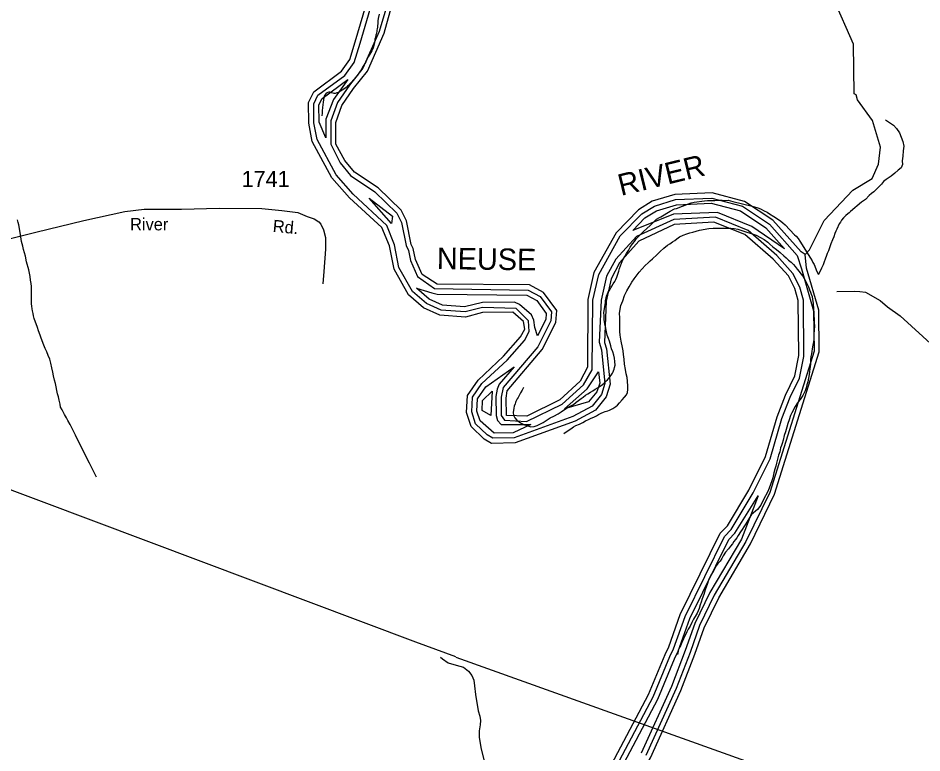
# Model space of a CAD drawing. Extents: x 2206922 to 2357709, y 510027 to 673830.
# Drawn here: x 2329174 to 2336184, y 547095 to 552793 of the extents above; entities that cross this region are included whole.
import ezdxf

# ---------------------------------------------------------------- set-up
doc = ezdxf.new("R2010")
doc.units = 0
for name, color, linetype in [('Exist Hydrographic Buffer Line', 7, 'Continuous'), ('Exist Hydrographic Creek Single Shore', 7, 'Continuous'), ('Exist Hydrographic Misc Water Feature', 7, 'Continuous'), ('Exist Hydrographic River Shore', 7, 'Continuous'), ('Exist Hydrographic River Shore Label', 7, 'Continuous'), ('Exist Road Non-System Type 51', 7, 'Continuous'), ('Exist Road Secondary Type 51 Attributed', 7, 'Continuous'), ('Exist Road Secondary Type 51 Label', 7, 'Continuous'), ('Exist Road Secondary Type 51 Number Label', 7, 'Continuous'), ('Exist Utilities Electrical Transmission Line', 7, 'Continuous')]:
    doc.layers.add(name, color=color, linetype=linetype)

msp = doc.modelspace()

# ---------------------------------------------------------------- linework, layer by layer
at = {"layer": 'Exist Hydrographic Buffer Line'}
for points in [[(2332099, 553109.3), (2331974.9, 552690.5), (2331848.2, 552403.8), (2331744.2, 552272.2), (2331651.8, 552138.5), (2331599.1, 551996.2), (2331598.6, 551814.8), (2331671.4, 551670.9), (2331752, 551572.5), (2331941.5, 551446.1), (2332111.1, 551280.1), (2332147.6, 551207.4), (2332182.4, 551030.3), (2332200.7, 550992.4), (2332216.5, 550913.4), (2332271.2, 550788.9), (2332403.3, 550697.5), (2333130.6, 550684.1), (2333222.7, 550635.1), (2333310.4, 550514.3), (2333304.5, 550444.7), (2333204.2, 550244.8), (2332936.2, 549929), (2332919.2, 549852.7), (2332920.8, 549711.9), (2332947.1, 549675), (2333117.1, 549665.8), (2333393.7, 549798.6), (2333558.9, 549949.1), (2333625, 550066.8), (2333631.7, 550606.3), (2333677.5, 550805.1), (2333844, 551104.3), (2334010.1, 551274.7), (2334108.5, 551336), (2334273.5, 551386), (2334553.4, 551397.3), (2334792.3, 551335.1), (2335000.3, 551196.3), (2335215.8, 550953.1)], [(2332340.5, 550580.5), (2332232.3, 550672.5), (2332127.7, 550859.6), (2332094, 551035.6), (2332032.7, 551185.4), (2331771.5, 551427.5), (2331640.7, 551577.7), (2331493, 551850.9), (2331468.6, 551981.4), (2331466.8, 552129.1), (2331499.4, 552195.5), (2331706.5, 552349.4), (2331780.1, 552449.5), (2331826.3, 552597.7), (2331962.2, 553059.6)], [(2331559.5, 551864), (2331508.6, 551985.3), (2331507, 552120.2), (2331531, 552169.2), (2331730.5, 552317.2), (2331618.9, 552161.3), (2331561.5, 552009.7), (2331559.5, 551864)], [(2332069.6, 551200.8), (2331896.2, 551397.2), (2332078.3, 551256.2), (2332069.6, 551200.8)], [(2335117.5, 551003.9), (2334863.5, 551176.5), (2334597.9, 551286), (2334255.7, 551272.4), (2333941.4, 551146.8), (2334035.3, 551243.3), (2334125.1, 551299.2), (2334280.3, 551346.2), (2334548.9, 551357.1), (2334775.5, 551298.2), (2334973.8, 551165.9), (2335117.5, 551003.9)], [(2333789.2, 546943.2), (2334099, 547529.8), (2334227.6, 547842.2), (2334256.7, 547901.4), (2334346.8, 548153.2), (2334651.9, 548774.6), (2334705, 548828.1), (2334875.4, 549111.6), (2335006.6, 549375.5), (2335097.9, 549689.2), (2335161.6, 549852.7), (2335233.8, 550001.9), (2335268, 550170.5), (2335264.8, 550605), (2335237.3, 550706.4), (2335183.4, 550813.3), (2335059.3, 550951.8), (2334837, 551146.4), (2334583.6, 551248.7), (2334258.4, 551232.4), (2333969.9, 551099.5), (2333808.7, 550923.1), (2333738.4, 550791.1), (2333694.7, 550605.9), (2333680.7, 550279.8), (2333698.6, 550220.9), (2333725, 549959.3), (2333698, 549874.7), (2333624.8, 549784.9), (2333477.3, 549705), (2333021.3, 549538.6), (2332856, 549534.9), (2332811.9, 549560.5), (2332721.7, 549647.8), (2332692, 549741.4), (2332697.9, 549854.3), (2332771.3, 549959.6), (2332965.9, 550141.9), (2333100.9, 550294.4), (2333138, 550362.5), (2333133.3, 550446), (2333035.9, 550542.4), (2332776.3, 550549.2), (2332639.9, 550514.6), (2332453.9, 550528.5), (2332340.5, 550580.5)], [(2335215.8, 550953.1), (2335249, 550849.6), (2335343.7, 550523.1), (2335346.8, 550210.2), (2335003.5, 549115.5), (2334818.6, 548734.7), (2334573.3, 548319.3), (2334457.9, 548082.1), (2334385.5, 547874.9), (2334276.8, 547593.7), (2334042, 547075.1)], [(2333201.9, 550329.4), (2333181.8, 550393.3), (2333172.8, 550452.1), (2333155, 550491.4), (2333061.7, 550572.7), (2333023.8, 550590.8), (2332775.8, 550589.2), (2332636.2, 550555), (2332464, 550567.9), (2332362.1, 550614.6), (2332263.4, 550698.3), (2332381.9, 550663.6), (2332424, 550651.3), (2333120.5, 550644.2), (2333196, 550604.1), (2333269.4, 550502.9), (2333265.5, 550455.8), (2333201.9, 550329.4)], [(2332866.5, 549575.1), (2332757, 549669.5), (2332732.6, 549746.5), (2332737.5, 549840.8), (2332801.5, 549933.3), (2333020.3, 550089.9), (2332905.8, 549954.9), (2332888, 549917), (2332879.6, 549858.3), (2332880.8, 549711.4), (2332891.5, 549672.6), (2332920.8, 549643.2), (2333151.1, 549642), (2333013.7, 549578.4), (2332866.5, 549575.1)], [(2333411.5, 549762.7), (2333586, 549919.7), (2333675.8, 550049.3), (2333684.4, 549963.5), (2333662.3, 549894.2), (2333598.7, 549816.4), (2333411.5, 549762.7)], [(2332840.8, 549710.8), (2332772.8, 549751.7), (2332776.7, 549827.4), (2332851.5, 549900.9), (2332840.8, 549710.8)], [(2333824.7, 546924.6), (2334134.5, 547511.2), (2334264.1, 547825.8), (2334292.6, 547883.8), (2334383.5, 548137.6), (2334684.9, 548751.1), (2334733.5, 548799.9), (2334913.7, 549089.5), (2334783.3, 548753.7), (2334538.9, 548339.7), (2334421.8, 548099.7), (2334348, 547888.7), (2334240.1, 547609.2), (2334006.6, 547093.3)]]:
    msp.add_lwpolyline(points, dxfattribs=at)
at = {"layer": 'Exist Hydrographic Creek Single Shore'}
msp.add_lwpolyline([(2335278.7, 550961.3), (2335311.7, 550995.4), (2335425.7, 551223.1), (2335648.8, 551458.5), (2335797.7, 551549.9), (2335846.7, 551660.1), (2335861.9, 551792), (2335800.8, 551999.6), (2335682.9, 552158.9), (2335673.8, 552198), (2335656.8, 552207.1), (2335652.7, 552590.9), (2335499.8, 552939.1)], dxfattribs=at)
at = {"layer": 'Exist Hydrographic Misc Water Feature'}
for points in [[(2331973.5, 552824.5), (2331965.7, 552790.4), (2331964, 552772.4), (2331964.3, 552748.5)], [(2331964.3, 552748.5), (2331962.2, 552736.6), (2331960.8, 552722.2), (2331958.7, 552710.4), (2331956.7, 552700.6), (2331955, 552688.2), (2331953, 552678.4), (2331951.3, 552668.1), (2331949.1, 552660.3), (2331945.4, 552642.2), (2331941.7, 552630.2), (2331939.6, 552616.3), (2331937.8, 552602.4), (2331932.1, 552580.2), (2331928.2, 552562.1), (2331916.3, 552540), (2331900.5, 552513.9), (2331888.8, 552491.8), (2331877.3, 552471.6), (2331869.7, 552453.7), (2331855.6, 552427.4), (2331845.9, 552413.5), (2331836.3, 552395.5), (2331826.3, 552381.2), (2331816.4, 552365.2), (2331806.8, 552350.8), (2331792.6, 552334.8), (2331785, 552324.9), (2331770.9, 552308.8), (2331761.5, 552298.5), (2331749.2, 552286.5), (2331737.5, 552272.5), (2331729.3, 552266.4), (2331718, 552253.9), (2331707.7, 552246.1), (2331688.2, 552233.7), (2331679.8, 552229.6), (2331669.8, 552223.4), (2331660, 552217.6), (2331646, 552213.2), (2331633.9, 552209.4), (2331630, 552209.2), (2331624.1, 552209.2), (2331616.3, 552210.8), (2331604.2, 552214.6), (2331598.2, 552216.7), (2331592.3, 552218.9), (2331584.1, 552218.5), (2331576.1, 552216.4), (2331570.1, 552214.5), (2331560.3, 552206.2), (2331550.5, 552192.3), (2331544.7, 552178.2), (2331540.8, 552140.3), (2331535.5, 552100.1), (2331532, 552074.3), (2331532, 552056), (2331530.4, 552036)], [(2335902.3, 552003.2), (2335962.4, 551964.1), (2335986.8, 551936.5), (2336009.1, 551904.8), (2336023.5, 551871), (2336035.8, 551837.1), (2336042.5, 551801.3), (2336038.6, 551763.3), (2336035.4, 551723.2), (2336031.5, 551686.9), (2336032.1, 551659.3), (2336022, 551633.2), (2336000.5, 551612.9), (2335972.8, 551590.3), (2335944.9, 551568.2), (2335907.4, 551541.8)], [(2335907.4, 551541.8), (2335886.1, 551525.1), (2335870.1, 551506), (2335850.4, 551485.4), (2335830.3, 551466.6), (2335810.2, 551447.3), (2335792.4, 551432.6), (2335774.7, 551418.2), (2335745, 551387.8), (2335715.3, 551365.5), (2335630, 551294.4), (2335618.1, 551284.4), (2335608.2, 551276.2), (2335594.5, 551262), (2335576.4, 551244), (2335560.7, 551225.7), (2335551.2, 551211.7), (2335542.8, 551197.6), (2335523.5, 551157.5), (2335515.8, 551141.2), (2335508, 551123.4), (2335500.4, 551097.4), (2335490.7, 551073.2), (2335476.8, 551042.9), (2335469, 551018.9), (2335459.4, 550988.7), (2335449.7, 550966.7), (2335444, 550952.5), (2335432.1, 550922.7), (2335426.1, 550902.5), (2335416.5, 550880.4), (2335405, 550854.2), (2335381.2, 550806.2)], [(2333892.6, 550968.1), (2333908.1, 550992.2), (2333921.9, 551016.5), (2333939.3, 551042.6), (2333953.5, 551060.8), (2333971.1, 551084.9), (2334002.7, 551119), (2334024.8, 551139.2), (2334075.9, 551185.9), (2334111.8, 551222.3), (2334125.5, 551234.4), (2334147.2, 551246.5), (2334159.3, 551252.8), (2334230.5, 551295.6), (2334264.5, 551313.6), (2334280.7, 551318.1), (2334374, 551353.1), (2334394.1, 551361.1), (2334417.7, 551365.6), (2334497.7, 551376.3), (2334519.8, 551378.6), (2334539.9, 551378.9), (2334559.8, 551379.1), (2334577.6, 551379.3), (2334595.5, 551381.5), (2334617.6, 551381.4), (2334635.5, 551381.9), (2334659.5, 551379.9), (2334681.6, 551380.3), (2334699.6, 551376.3), (2334717.9, 551370.8), (2334865.9, 551334.3), (2334886.2, 551330.4), (2334910, 551320.8), (2334932.2, 551313), (2334960.1, 551299.4), (2334982.8, 551287.5), (2335000.5, 551275.9), (2335034.7, 551254.2), (2335071, 551232.5), (2335089, 551218.8), (2335105, 551205.1), (2335121.6, 551189.2), (2335196.1, 551113.9), (2335208.2, 551101.9), (2335222.7, 551084.3), (2335236.9, 551062.4), (2335320.1, 550931.4), (2335332, 550911.4), (2335338.6, 550897.4), (2335346.6, 550881.6), (2335369.1, 550827.9), (2335381.2, 550806.2)], [(2329293.7, 550484.8), (2329290, 550502.9), (2329285.7, 550523), (2329283.6, 550538.7), (2329279.1, 550560.8), (2329278.7, 550578.7), (2329278.7, 550598.6), (2329278.5, 550620.6), (2329278.1, 550638.9), (2329278.1, 550658.8), (2329277.7, 550674.6), (2329277.5, 550688.8), (2329277.7, 550712.7), (2329275.4, 550734.6), (2329270.7, 550760.8), (2329266.4, 550788.6), (2329256.3, 550842.4), (2329239.3, 550904.2), (2329231.1, 550946), (2329216.1, 550999.8), (2329210.4, 551023.8), (2329199.7, 551059.8), (2329191.1, 551115.4), (2329178.4, 551189.5), (2329174.1, 551207.2), (2329170.2, 551229.3)], [(2333405.6, 549571.5), (2333431.6, 549589.8), (2333461.3, 549608.1), (2333481, 549624.2), (2333498.9, 549634.5), (2333526.5, 549644.9), (2333554.4, 549656.9), (2333574.5, 549669.3), (2333598.1, 549681.6), (2333618.2, 549691.9), (2333639.9, 549700), (2333660, 549708.3), (2333674, 549718.4), (2333695.5, 549730.6), (2333714, 549738.7), (2333727.3, 549742.8), (2333747.6, 549749.1), (2333761.3, 549753.1), (2333787.2, 549765.4), (2333809.5, 549781.5), (2333823, 549791.7), (2333838.8, 549810), (2333858.7, 549832.1), (2333876.6, 549852.6), (2333892.1, 549872.5), (2333899.9, 549890.8), (2333903.8, 549914.6), (2333903.6, 549938.5), (2333901, 549976.7), (2333897.1, 550006.4), (2333888.5, 550034.5), (2333883.9, 550068.4), (2333877.8, 550110.3), (2333873.5, 550148.2), (2333868.8, 550184.2), (2333866.5, 550214.2), (2333860.4, 550238.2), (2333851.5, 550287.8), (2333843.6, 550333.6), (2333841.1, 550361.9), (2333840.5, 550389.6), (2333840.5, 550419.6), (2333840.1, 550443.6), (2333839.7, 550471.6), (2333839, 550503.8), (2333843.1, 550535.6), (2333848.7, 550563.6), (2333864.3, 550601.8), (2333877.8, 550641.9), (2333895.4, 550678.2), (2333913.5, 550710.3), (2333934.8, 550744.4), (2333952.2, 550772.6), (2333974, 550803), (2333990, 550822.9), (2334013.5, 550849.4), (2334037.5, 550873.8), (2334061.1, 550895.7), (2334077.1, 550912), (2334092.7, 550926.3), (2334126.5, 550958.5), (2334153.8, 550982.8), (2334181.7, 551009), (2334209.6, 551031.5), (2334229.5, 551043.6), (2334249.4, 551058), (2334267, 551070), (2334283, 551082.1), (2334304.5, 551096.3), (2334330.8, 551110.7), (2334360.5, 551120.8), (2334382.4, 551127.3), (2334406.2, 551133.4), (2334458.5, 551147.8), (2334531.9, 551162.7), (2334564.1, 551165.2), (2334597.7, 551165.4), (2334625.8, 551165.6), (2334658, 551164.1), (2334701.9, 551164.7), (2334727.9, 551160.8), (2334756, 551155.4), (2334780, 551149.3), (2334898.1, 551108.8), (2334930.5, 551093.1), (2334958.8, 551077.4), (2334989, 551055.8), (2335005, 551040.1), (2335027.1, 551020.1), (2335055.8, 550998.3), (2335083.7, 550976.7), (2335112, 550951), (2335130.5, 550933.2), (2335148.1, 550917.5), (2335168.4, 550901.5), (2335186.8, 550882.1), (2335200.8, 550866.2), (2335214.9, 550846.3), (2335231.6, 550828.4), (2335245.1, 550810.5)], [(2333094.3, 549928.1), (2333082, 549908), (2333070.5, 549887.9), (2333062.3, 549871.7), (2333051, 549851.5), (2333045.1, 549841.4), (2333034.8, 549821.4), (2333031.5, 549811.4), (2333029.5, 549801.2), (2333021.7, 549785.3), (2333017.8, 549769.3), (2333013.7, 549735.4), (2333016, 549715.2), (2333026.4, 549693.4), (2333042.8, 549675.5), (2333060.7, 549661.8), (2333070.7, 549653.8), (2333101.3, 549640), (2333113, 549636.6), (2333123, 549632.6), (2333135.5, 549628.7), (2333149.2, 549624.6), (2333175.1, 549627.2), (2333199.1, 549635.3), (2333224.9, 549647.7), (2333244.8, 549657.7), (2333270.4, 549674.1), (2333300.2, 549694.3), (2333328.3, 549706.8), (2333362.3, 549725.2), (2333385.7, 549741.1), (2333411.5, 549757.5), (2333445.5, 549777.9), (2333481, 549798.1), (2333503, 549814.3), (2333520.6, 549828.7), (2333540.3, 549844.8), (2333556.5, 549854.9), (2333574.1, 549869.3), (2333592.4, 549879.5), (2333611.8, 549891.6), (2333631.9, 549902), (2333650, 549915.9), (2333671.9, 549928), (2333687.7, 549938.2), (2333705.3, 549952.6), (2333721.3, 549964.7), (2333733, 549976.8), (2333744.9, 549988.7), (2333756.6, 550003.2), (2333764.6, 550012.9), (2333772.6, 550025.1), (2333782.7, 550039.4), (2333788.2, 550049.2), (2333792.5, 550057.4), (2333796, 550071.5), (2333800.3, 550083.4), (2333803.6, 550101.6), (2333801.5, 550129.5), (2333799.5, 550155.4), (2333793.1, 550179.4), (2333786.3, 550205.1), (2333776.5, 550229.3), (2333769.9, 550251), (2333766, 550271.1), (2333759.7, 550287), (2333751.5, 550308.9), (2333743.5, 550334.9), (2333737.1, 550360.6), (2333728.3, 550402.4), (2333724, 550420.5), (2333722, 550440.3), (2333719.9, 550454.4), (2333719.7, 550468.6), (2333719.7, 550486.5), (2333717.4, 550508.3), (2333719.1, 550526.3), (2333720.7, 550538.6), (2333723, 550556.5), (2333726.5, 550570.6), (2333730.6, 550590.2), (2333730.6, 550602.4), (2333734.3, 550622.5), (2333737.7, 550640.7), (2333743.9, 550656.4), (2333753.7, 550674.8), (2333759.3, 550680.8), (2333769.5, 550700.8), (2333777.3, 550715), (2333788.8, 550733.1), (2333800.9, 550751.2), (2333808.7, 550765), (2333816.3, 550783.3), (2333824.1, 550807.3), (2333832.1, 550831.3), (2333837.8, 550851.5), (2333853.2, 550891.7), (2333864.9, 550919.6), (2333878.6, 550945.9), (2333892.6, 550968.1)], [(2335245.1, 550810.5), (2335259.6, 550790.9), (2335271.5, 550772.9), (2335279.9, 550757), (2335286.1, 550745.1), (2335296.3, 550725.3), (2335304.3, 550709.1), (2335312.5, 550687.2), (2335319.1, 550667.6), (2335324.8, 550653.7), (2335331.4, 550633.7), (2335335.3, 550611.6), (2335339.6, 550581.8), (2335342.3, 550535.6), (2335344.7, 550509.6), (2335344.5, 550483.7), (2335347, 550461.9), (2335347.4, 550433.8), (2335350.1, 550403.8), (2335348, 550374.1), (2335346.4, 550346), (2335344.7, 550298), (2335331.6, 550229.8), (2335329.8, 550207.7), (2335325.9, 550189.7), (2335322.6, 550169.9), (2335320.5, 550141.9), (2335318.5, 550129.6), (2335319.1, 550107.6), (2335317.3, 550091.6), (2335313.4, 550073.6), (2335311.3, 550053.6), (2335309.9, 550029.5), (2335298.6, 549971.6), (2335292.2, 549949.4), (2335286.5, 549925.5), (2335279.1, 549903.6), (2335271.3, 549887.3), (2335259.4, 549867.2), (2335239.5, 549836.9), (2335225.8, 549820.7), (2335214.3, 549802.6), (2335200.4, 549780.8), (2335175, 549732.3), (2335165.3, 549712.2), (2335153.6, 549678.3), (2335143.8, 549650.2), (2335136.4, 549620.1), (2335124.3, 549583.8), (2335115.1, 549556), (2335107.3, 549519.8), (2335099.5, 549495.4), (2335093.8, 549479.7), (2335087.8, 549461.5), (2335080.4, 549429.4), (2335070.4, 549403.3), (2335063, 549373.2), (2335055.4, 549343.1), (2335049.3, 549319.3), (2335041.9, 549295.3), (2335034.3, 549267.2), (2335026.7, 549229), (2335018.7, 549205.1), (2335009.1, 549176.9), (2334999.2, 549148.8), (2334985.9, 549116.8), (2334958.4, 549066.6), (2334933, 549016.1), (2334907.2, 548981.8), (2334861.6, 548943.2), (2334849.9, 548923.1), (2334834.2, 548897.1), (2334818.4, 548871.1), (2334802.6, 548848.7), (2334788.8, 548826.5), (2334776.7, 548808.4), (2334759.3, 548782.3), (2334747.8, 548764.1), (2334737.8, 548750.2), (2334725.9, 548734.2), (2334714.2, 548717.7), (2334698, 548697.8), (2334682.8, 548677.8), (2334661.1, 548651.5), (2334643.3, 548623.3), (2334631.4, 548603.2), (2334617.8, 548583), (2334601.6, 548563.1), (2334588.1, 548544.8), (2334578.3, 548526.5), (2334564.5, 548502.6), (2334546.9, 548474.4), (2334530.9, 548441.9), (2334517.6, 548400.1), (2334502, 548359.9), (2334492.5, 548323.6), (2334478.8, 548289.6), (2334471.4, 548263.5), (2334464, 548243.6), (2334456.7, 548215.5)], [(2329782.9, 549232.9), (2329728, 549342.1), (2329683, 549427.5), (2329619.9, 549559.1), (2329576.8, 549642.6), (2329560.4, 549672.2), (2329547.9, 549694), (2329534, 549720), (2329525.6, 549735.9), (2329515.7, 549755.6), (2329503.4, 549775.7), (2329499.3, 549799.4), (2329492.8, 549829.6), (2329486.4, 549855.3), (2329480.2, 549879.4), (2329473.9, 549905.4), (2329469.6, 549933.2), (2329463.2, 549961), (2329455.2, 549986.9), (2329449.1, 550019), (2329442.7, 550046.8), (2329436, 550080.7), (2329428, 550116.7), (2329419.1, 550148.4), (2329407.3, 550176.2), (2329397, 550206.2), (2329384.7, 550231.9), (2329374, 550257.8), (2329353.7, 550311.6), (2329345.3, 550335.5), (2329331, 550367.3), (2329323, 550393.3), (2329298.2, 550463.1), (2329293.7, 550484.8)], [(2334456.7, 548215.5), (2334440, 548179.4), (2334432.3, 548165.2), (2334412.4, 548132.9), (2334399.9, 548106.8), (2334385.5, 548078.6), (2334371.2, 548054.3), (2334361.1, 548034.4), (2334353.1, 548016.6), (2334340.8, 547994.1), (2334330.8, 547972.1), (2334320.7, 547952.1), (2334312.5, 547931.8), (2334306.8, 547917.7), (2334299, 547903.8), (2334293, 547883.6), (2334287.5, 547859.7)], [(2332448.6, 547837.9), (2332465, 547824.1), (2332508.9, 547794.4), (2332571.2, 547775.3), (2332627.2, 547759.9), (2332667.8, 547728.3), (2332692, 547696.7), (2332708.6, 547658.5), (2332714.7, 547616.6), (2332721.5, 547547.1), (2332741, 547421.3), (2332755.1, 547379.4), (2332760.1, 547347.4), (2332758.2, 547313.2), (2332748.4, 547267.3), (2332749, 547217.3), (2332763.7, 547137.7), (2332789.2, 547032.1)]]:
    msp.add_lwpolyline(points, dxfattribs=at)
at = {"layer": 'Exist Hydrographic River Shore'}
for points in [[(2334191.1, 547858.7), (2334220.8, 547919.1), (2334309.8, 548168.8), (2334618.9, 548798.2), (2334676.9, 548856.3), (2334840.7, 549132), (2334970.7, 549393.3), (2335059.7, 549702), (2335124.7, 549868.7), (2335197.7, 550019.4), (2335228.9, 550178.2), (2335224.8, 550604.6), (2335198.7, 550695.5), (2335147.9, 550795.1), (2335029.8, 550924.9), (2334810.8, 551116.3), (2334568.8, 551211.5), (2334260.8, 551192.5), (2333986.7, 551063.3), (2333838.8, 550896.6), (2333773.8, 550772.5), (2333733.8, 550597), (2333720.7, 550278.1), (2333737.7, 550229.6), (2333765.8, 549955.1), (2333733.8, 549855.3), (2333650.8, 549753.6), (2333493.7, 549668.4), (2333028.7, 549498.7), (2332845.8, 549494.6), (2332787.7, 549528.4), (2332686.6, 549626.1), (2332651.8, 549736.2), (2332658.8, 549867.7), (2332740.8, 549985.9), (2332938.7, 550171.1), (2333070.7, 550320.8), (2333102.7, 550381.2), (2333093.7, 550439.9), (2333009.8, 550512), (2332776.7, 550509.2), (2332643.8, 550474.3), (2332443.7, 550489.2), (2332318.8, 550546.4), (2332200.7, 550646.7), (2332089.7, 550845.7), (2332054.7, 551028.1), (2331995.8, 551170.1), (2331742.8, 551399.5), (2331607.7, 551554.8), (2331454.7, 551837.4), (2331428.7, 551977.4), (2331426.8, 552138.2), (2331467.6, 552221.8), (2331682.7, 552381.5), (2331747.7, 552472.7), (2331787.7, 552608.9), (2331924.7, 553073.9)], [(2335278.7, 550961.3), (2335245.7, 550979.6), (2335026.7, 551226.7), (2334808.7, 551372.1), (2334557.7, 551437.5), (2334266.8, 551425.8), (2334091.7, 551372.7), (2333984.8, 551306.1), (2333811.8, 551128.4), (2333639.7, 550819.6), (2333591.7, 550610.9), (2333589.7, 550085.8), (2333531.7, 549978.4), (2333375.8, 549834.3), (2333118.7, 549705.8), (2332960.8, 549712.5), (2332958.8, 549847.1), (2332966.7, 549903.1), (2333237.8, 550222.6), (2333343.8, 550433.6), (2333351.8, 550525.7), (2333249.7, 550666.1), (2333140.8, 550724), (2332424.8, 550731.2), (2332307.7, 550805.3), (2332255.8, 550921.3), (2332238.8, 551006), (2332221.8, 551038.1), (2332185.7, 551220.4), (2332143.7, 551304), (2331966.7, 551477.4), (2331782.8, 551597.9), (2331706.7, 551690), (2331638.6, 551815.3), (2331636.8, 551982.6), (2331684.8, 552115.8), (2331775.8, 552247.4), (2331882.6, 552382.9), (2332012.6, 552677), (2332124.8, 553078.7)], [(2334423, 547861.1), (2334493.8, 548064.6), (2334607.8, 548299), (2334853.8, 548715.8), (2335040.9, 549100.7), (2335386.8, 550204.3), (2335383.7, 550529), (2335288.8, 550853.3), (2335278.7, 550961.3)], [(2333574.7, 546554.1), (2333623.7, 546710.3), (2333753.7, 546961.7), (2334063.8, 547548.5), (2334191.1, 547858.7)], [(2334110.7, 544816.7), (2334175.7, 544901.4), (2334224.7, 545028.1), (2334214.9, 545211.4), (2334195.8, 545384.7), (2334144.8, 545477.7), (2334135.8, 545510.2), (2334033.8, 545693.2), (2333915.7, 545908.2), (2333846.8, 546089.2), (2333802.7, 546330.3), (2333799.9, 546573), (2334077.7, 547056.8), (2334313.7, 547578.3), (2334423, 547861.1)]]:
    msp.add_lwpolyline(points, dxfattribs=at)
at = {"layer": 'Exist Road Non-System Type 51'}
for points in [[(2335524.5, 550674.5), (2335664.2, 550675.9), (2335702.4, 550672.4), (2335746.4, 550666.8), (2335859, 550604.1), (2335917.4, 550554.7)], [(2335916.8, 550553.1), (2336015.6, 550484.2), (2336278.4, 550243.6)]]:
    msp.add_lwpolyline(points, dxfattribs=at)
at = {"layer": 'Exist Road Secondary Type 51 Attributed'}
msp.add_lwpolyline([(2329063.7, 551070.7), (2329310.8, 551133.3), (2329683.7, 551223.3), (2330002.7, 551292.6), (2330150.4, 551312.2), (2330440.3, 551311.3), (2330732, 551318.5), (2331063.8, 551316.1), (2331220, 551301.8), (2331342.1, 551285.1), (2331416.3, 551255.9), (2331470.5, 551236.5), (2331504.9, 551212.9), (2331521, 551195.1), (2331543.4, 551151.4), (2331558, 551091.6), (2331559, 551001.6), (2331544.8, 550827.6), (2331535.9, 550731.4)], dxfattribs=at)
at = {"layer": 'Exist Utilities Electrical Transmission Line'}
msp.add_line((2332569, 547838.1), (2335962.3, 546625.2), dxfattribs=at)
msp.add_lwpolyline([(2332568.5, 547840), (2332257.4, 547954.7), (2328092.9, 549519.1), (2326225.9, 550216)], dxfattribs=at)

# ---------------------------------------------------------------- texts
at = {"layer": 'Exist Hydrographic River Shore Label'}
for s, rotation, p in [('RIVER', 13.67844, (2333849.3, 551414)), ('NEUSE', 359.20337, (2332420.5, 550847.1))]:
    msp.add_text(s, height=167.32, rotation=rotation, dxfattribs=at).set_placement(p)
at = {"layer": 'Exist Road Secondary Type 51 Label'}
for s, rotation, p in [('River', 359.82233, (2330042.3, 551148)), ('Rd.', 354.76879, (2331145.8, 551135.4))]:
    msp.add_text(s, height=95, rotation=rotation, dxfattribs=at).set_placement(p)
at = {"layer": 'Exist Road Secondary Type 51 Number Label'}
msp.add_text('1741', height=125, dxfattribs=at).set_placement((2330907.3, 551483.5))

doc.saveas('drawing.dxf')
